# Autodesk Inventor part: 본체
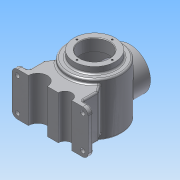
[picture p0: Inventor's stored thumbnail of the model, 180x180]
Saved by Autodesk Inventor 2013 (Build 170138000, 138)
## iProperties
Created: 2018-08
Part Number: 본체
Material: 알루미늄 6061
Document SubType Name: Modeling
Designer: Administrator
Density: 2.71 g/cm^3
Mass: 1886.06 g
Surface Area: 1087.48 cm^2
Volume: 695.964 cm^3
Author: Administrator
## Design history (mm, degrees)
sketch "스케치1"
  geometry: L1 (0, 0)-(50, 0); L2 (50, 0)-(50, -96.671); L3 (0, -108)-(0, 0); A1 r 116 centre (0, 8) between (0, -108) and (50, -96.671); A2 r 116 centre (0, 8) between (0, -108) and (50, -96.671)
  constraints: 6 end point, 4 point on circle, 2 centre point, 1 horizontal, 1 parallel, 1 perpendicular, 1 point on line
revolve "회전1" sketch "스케치1" stored, may be unused: angle "d3" = 90 deg
sketch "스케치2"
  geometry: C1 r 50 at (0, 0) reference; C2 r 38 at (0, 0)
  constraints: 1 centre point, 1 coincident
  dimensions: "d4" = 76 diameter of C2
extrude "돌출1" join sketch "스케치2" distance "d5" = 12; taper "d6" = 0 deg
sketch "스케치3"
  geometry: C1 r 38 at (0, 0) reference; C2 r 27 at (0, 0)
  constraints: 1 centre point, 1 coincident
  dimensions: "d7" = 54 diameter of C2
extrude "돌출2" cut sketch "스케치3" distance "d8" = 22; taper "d9" = 0 deg
sketch "스케치4"
  geometry: L1 (-27, -10)-(27, -10) reference; L2 (0, -10)-(40, -10); L3 (40, -10)-(40, -90.163); L4 (0, -98)-(0, -10); A1 r 116 centre (0, 8) between (-50, -96.671) and (50, -96.671) reference; A2 r 106 centre (0, 8) between (0, -98) and (40, -90.163); 1 further point
  constraints: 6 end point, 2 point on circle, 1 centre point, 1 horizontal, 1 midpoint, 1 parallel, 1 perpendicular
  dimensions: "d10" = 10 radial gap between concentric circles of A1 A2; "d11" = 40 distance between parallel lines of L4 L3
revolve "회전2" sketch "스케치4" stored, may be unused: angle "d12" = 90 deg
node "작업 평면1"
sketch "스케치5"
  geometry: L1 (38, 12)-(-38, 12) reference; L2 (-50, 0)-(50, 0) reference; C1 r 38 at (0, -50); 1 further point
  constraints: 1 centre point
  dimensions: "d14" = 76 diameter of C1; "d15" = 50 distance from line of C1.centre L2
extrude "돌출3" join sketch "스케치5" stored distance "d16" = 50 (= d15); taper "d17" = 0 deg
sketch "스케치6"
  geometry: C1 r 38 at (0, 0) reference; C2 r 27 at (0, 0); 1 further point
  constraints: 1 centre point, 1 coincident
  dimensions: "d18" = 54 diameter of C2
extrude "돌출4" cut sketch "스케치6" stored distance "d19" = 22; taper "d20" = 0 deg
sketch "스케치7"
  geometry: C1 r 27 at (0, 0) reference; 2 further points
  dimensions: "d21" = 32.5 distance of C1.centre point (0, 32.5)
hole "구멍1" sketch "스케치7" at (0, 32.5) diameter "d22" = 3.242; stored, may be unused: countersink angle "d26" = 90 deg, drill point angle "d28" = 118 deg; dims "d23" = 8, "d24" = 4, "d25" = 2, "d27" = 10
sketch "스케치8"
  geometry: C1 r 27 at (0, 0) reference; 1 further point
  dimensions: "d32" = 32.5 distance of C1.centre point (0, 32.5)
hole "구멍2" sketch "스케치8" at (0, 32.5) diameter "d33" = 3.242; stored, may be unused: countersink angle "d37" = 90 deg, drill point angle "d39" = 118 deg; dims "d34" = 8, "d35" = 4, "d36" = 2, "d38" = 10
node "작업 평면2"
sketch "스케치9"
  geometry: L1 (-50, 0)-(50, 0) reference; L2 (-70, -8)-(70, -8); L3 (70, -8)-(70, -88); L4 (70, -88)-(-70, -88); L5 (-70, -88)-(-70, -8); 1 further point
  constraints: 8 end point, 2 parallel, 1 horizontal, 1 perpendicular
  dimensions: "d44" = 8 distance between parallel lines of L2 L1; "d45" = 140 distance between parallel lines of L5 L3; "d46" = 70 distance from line of point (0, 0) L5; "d47" = 80 distance between parallel lines of L2 L4
extrude "돌출5" join sketch "스케치9" distance "d48" = 10; taper "d49" = 0 deg
sketch "스케치11"
  geometry: L1 (0, 10)-(140, 10) reference; L2 (140, 10)-(109.62, 53.386); L3 (140, 10)-(192.965, 10); L4 (109.62, 53.386)-(70, 33.165); L5 (70, 33.165)-(70, 10); 1 further point
  constraints: 8 end point, 1 equal length, 1 horizontal, 1 midpoint
  dimensions: "d52" = 125 deg angle of L3 L2
feature "리브1" sketch "스케치11" dims "d53" = 1, "d54" = 80, "d55" = 0, "d56" = 0, "d57" = 1, "d58" = 1
sketch "스케치12"
  geometry: L1 (140, 10)-(120, 10); L2 (120, 10)-(120, 53.415); L3 (120, 53.415)-(140, 53.415); L4 (140, 53.415)-(140, 10)
  constraints: 8 end point, 2 parallel, 1 horizontal, 1 perpendicular
  dimensions: "d59" = 20 distance of L2.end L3.end
extrude "돌출6" cut sketch "스케치12" stored distance "d60" = 10; taper "d61" = 0 deg
sketch "스케치13"
  geometry: L1 (70, -8)-(-70, -8) reference; L2 (-70, -88)-(70, -88) reference; L3 (70, -88)-(70, -8) reference; C1 r 4 at (60, -18); C2 r 4 at (60, -78); 1 further point
  constraints: 2 centre point
  dimensions: "d62" = 8 diameter of C1; "d63" = 8 diameter of C2; "d64" = 10 distance from line of L1 C1.centre; "d65" = 10 distance from line of L3 C1.centre; "d66" = 10 distance from line of L3 C2.centre; "d67" = 10 distance from line of L2 C2.centre
extrude "돌출7" cut sketch "스케치13" distance "d68" = 10; taper "d69" = 0 deg
sketch "스케치14"
  geometry: L1 (140, 0)-(0, 0) reference; L2 (0, 0)-(140, 0) reference; C1 r 12.5 at (42.5, 0); C2 r 17.5 at (92.5, 0); A1 r 50 centre (70, 82) between (29.696, 52.41) and (110.304, 52.41) reference; A2 r 50 centre (70, 82) between (110.304, 52.41) and (29.696, 52.41) reference
  constraints: 2 centre point, 1 point on line
  dimensions: "d70" = 25 diameter of C1; "d71" = 35 diameter of C2; "d72" = 27.5 horizontal distance of C1.centre A1.centre; "d73" = 22.5 horizontal distance of A1.centre C2.centre
extrude "돌출8" cut sketch "스케치14" stored distance "d74" = 10; taper "d75" = 0 deg
chamfer "모따기1" distance "d76" = 1; stored, may be unused: second distance "d77" = 2, angle "d78" = 45 deg
fillet "모깎기1" dims "d79" = 3
fillet "모깎기2" dims "d80" = 3
chamfer "모따기2" distance "d81" = 1; stored, may be unused: second distance "d82" = 2, angle "d83" = 45 deg
fillet "모깎기3" dims "d84" = 3
fillet "모깎기4" dims "d85" = 10
fillet "모깎기5" dims "d86" = 3
fillet "모깎기6" dims "d87" = 3
fillet "모깎기7" dims "d88" = 3
node "작업 평면3"
sketch "스케치15"
  geometry: C1 r 32.5 at (0, 0); 1 further point
  constraints: 1 centre point, 1 coincident, 1 other
  dimensions: "d90" = 65 diameter of C1
feature "엠보싱1" sketch "스케치15" dims "d91" = 0.5, "d92" = 0
node "솔리드1"
pattern_circular "원형 패턴1" dims angle "d30" = 360 deg
pattern_circular "원형 패턴2" dims angle "d41" = 360 deg
mirror "대칭1"
mirror "대칭2"
mirror "대칭3"
other parameters: "d2" = 232, "d13" = 65, "d43" = -82, "d89" = -108
